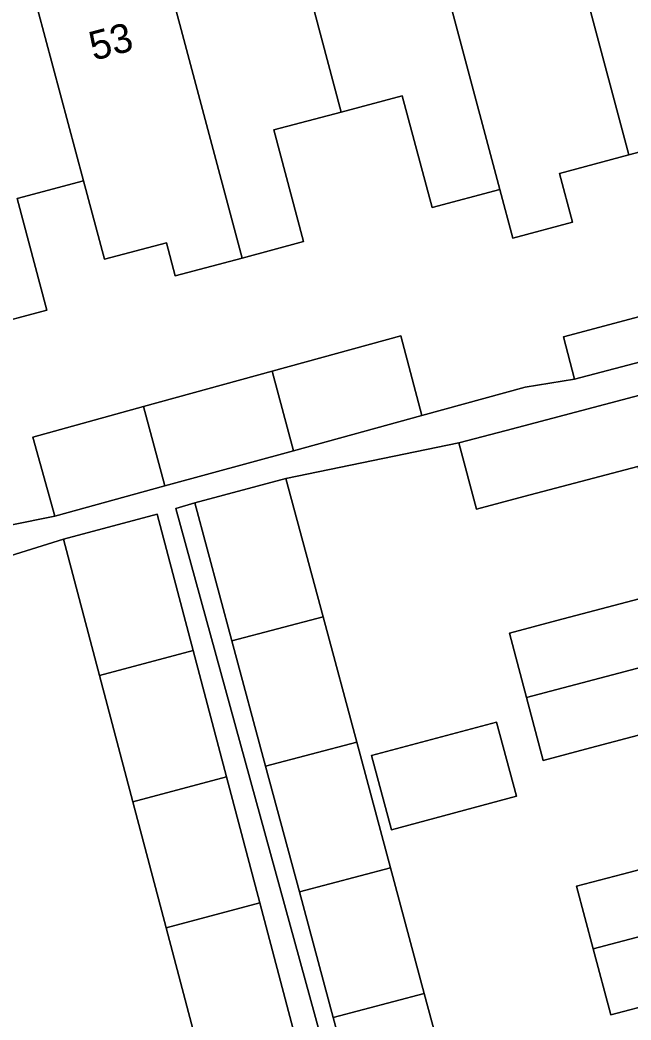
# Model space of a CAD drawing. Extents: x 162542 to 163147, y 380779 to 381521.
# Drawn here: x 162943.37 to 162964.52, y 381061.15 to 381095.77 of the extents above; entities that cross this region are included whole.
import ezdxf

# ---------------------------------------------------------------- set-up
doc = ezdxf.new("R2010")
doc.units = 0
for name, color, linetype in [('IMGEO_Erf', 7, 'Continuous'), ('IMGEO_Pand', 7, 'Continuous'), ('IMGEO_Pand_nummerreeks', 7, 'Continuous'), ('IMGEO_Voetpad_open', 7, 'Continuous')]:
    doc.layers.add(name, color=color, linetype=linetype)

msp = doc.modelspace()

# ---------------------------------------------------------------- linework, layer by layer
at = {"layer": 'IMGEO_Erf'}
for points in [[(162966.533, 381091.654), (162964.441, 381091.096), (162962.04, 381090.455), (162962.49, 381088.768), (162960.429, 381088.219), (162959.979, 381089.905), (162957.634, 381089.28), (162956.604, 381093.145), (162954.49, 381092.581), (162952.16, 381091.96), (162953.19, 381088.095), (162951.058, 381087.526), (162948.745, 381086.909), (162948.439, 381088.057), (162946.293, 381087.485), (162945.569, 381090.202), (162943.27, 381089.589), (162944.3, 381085.724), (162942.136, 381085.147)], [(162943.031, 381078.285), (162944.574, 381078.593), (162943.821, 381081.328), (162947.65, 381082.383), (162952.101, 381083.608), (162956.552, 381084.834), (162957.285, 381082.08), (162960.856, 381083.06), (162962.567, 381083.332), (162962.18, 381084.798), (162965.856, 381085.778)], [(162964.758, 381080.313), (162960.804, 381079.269), (162959.168, 381078.837), (162958.559, 381081.13), (162952.576, 381079.901), (162953.862, 381075.111), (162955.028, 381070.767), (162956.197, 381066.415), (162957.364, 381062.069), (162958.531, 381057.722), (162959.699, 381053.373), (162960.867, 381049.024), (162962.035, 381044.676), (162963.202, 381040.328), (162964.368, 381035.987), (162963.874, 381035.856), (162963.988, 381035.424), (162965.053, 381031.394)], [(162949.589, 381059.97), (162948.434, 381064.339), (162947.28, 381068.705), (162946.126, 381073.072), (162944.876, 381077.8), (162939.108, 381076.001), (162939.716, 381073.724), (162937.801, 381073.209), (162933.966, 381072.177), (162934.559, 381069.971), (162935.129, 381067.853), (162938.991, 381068.892), (162940.87, 381069.398), (162941.471, 381067.148), (162942.049, 381064.981), (162940.178, 381064.477), (162936.303, 381063.434), (162936.892, 381061.244), (162937.479, 381059.064)], [(162967.006, 381071.597), (162963.116, 381070.57), (162961.477, 381070.137), (162960.899, 381072.316), (162960.308, 381074.542), (162961.952, 381074.976), (162965.892, 381076.017)], [(162965.399, 381061.744), (162963.817, 381061.326), (162963.21, 381063.612), (162962.634, 381065.78), (162964.222, 381066.2), (162968.157, 381067.24)]]:
    msp.add_lwpolyline(points, dxfattribs=at)
for points in [[(162954.212, 381061.238), (162953.043, 381065.583), (162951.872, 381069.935), (162950.704, 381074.277), (162949.419, 381079.055), (162948.769, 381078.858), (162959.598, 381039.377), (162960.061, 381039.499), (162958.891, 381043.846), (162957.722, 381048.194), (162956.552, 381052.542), (162955.382, 381056.891)], [(162956.233, 381067.737), (162955.543, 381070.304), (162959.861, 381071.464), (162960.551, 381068.896)]]:
    msp.add_lwpolyline(points, close=True, dxfattribs=at)
at = {"layer": 'IMGEO_Pand'}
for points in [[(162964.441, 381091.096), (162966.533, 381091.654), (162968.842, 381092.269), (162965.956, 381103.091), (162961.56, 381101.919)], [(162964.441, 381091.096), (162961.56, 381101.919), (162957.099, 381100.729), (162959.979, 381089.905), (162960.429, 381088.219), (162962.49, 381088.768), (162962.04, 381090.455)], [(162952.638, 381099.539), (162954.49, 381092.581), (162956.604, 381093.145), (162957.634, 381089.28), (162959.979, 381089.905), (162957.099, 381100.729)], [(162952.638, 381099.539), (162948.177, 381098.349), (162951.058, 381087.526), (162953.19, 381088.095), (162952.16, 381091.96), (162954.49, 381092.581)], [(162948.177, 381098.349), (162943.717, 381097.16), (162945.569, 381090.202), (162946.293, 381087.485), (162948.439, 381088.057), (162948.745, 381086.909), (162951.058, 381087.526)], [(162943.717, 381097.16), (162939.255, 381095.97), (162942.136, 381085.147), (162944.3, 381085.724), (162943.27, 381089.589), (162945.569, 381090.202)], [(162962.18, 381084.798), (162962.567, 381083.332), (162966.249, 381084.305), (162965.856, 381085.778)], [(162952.833, 381080.859), (162957.285, 381082.08), (162956.552, 381084.834), (162952.101, 381083.608)], [(162965.332, 381078.14), (162972.251, 381079.967), (162971.052, 381084.43), (162966.218, 381083.153), (162960.198, 381081.563), (162958.559, 381081.13), (162959.168, 381078.837), (162960.804, 381079.269), (162964.758, 381080.313)], [(162952.833, 381080.859), (162952.101, 381083.608), (162947.65, 381082.383), (162948.381, 381079.637)], [(162948.381, 381079.637), (162947.65, 381082.383), (162943.821, 381081.328), (162944.574, 381078.593)], [(162953.862, 381075.111), (162952.576, 381079.901), (162949.419, 381079.055), (162950.704, 381074.277)], [(162965.332, 381078.14), (162965.892, 381076.017), (162961.952, 381074.976), (162960.308, 381074.542), (162960.899, 381072.316), (162973.42, 381075.619), (162972.251, 381079.967)], [(162949.366, 381073.941), (162948.119, 381078.661), (162944.876, 381077.8), (162946.126, 381073.072)], [(162960.899, 381072.316), (162961.477, 381070.137), (162963.116, 381070.57), (162967.006, 381071.597), (162967.581, 381069.421), (162974.588, 381071.271), (162973.42, 381075.619)], [(162953.862, 381075.111), (162950.704, 381074.277), (162951.872, 381069.935), (162955.028, 381070.767)], [(162950.521, 381069.574), (162949.366, 381073.941), (162946.126, 381073.072), (162947.28, 381068.705)], [(162960.551, 381068.896), (162959.861, 381071.464), (162955.543, 381070.304), (162956.233, 381067.737)], [(162963.21, 381063.612), (162975.757, 381066.923), (162974.588, 381071.271), (162967.581, 381069.421), (162968.157, 381067.24), (162964.222, 381066.2), (162962.634, 381065.78)], [(162955.028, 381070.767), (162951.872, 381069.935), (162953.043, 381065.583), (162956.197, 381066.415)], [(162950.521, 381069.574), (162947.28, 381068.705), (162948.434, 381064.339), (162951.675, 381065.207)], [(162963.21, 381063.612), (162963.817, 381061.326), (162965.399, 381061.744), (162969.326, 381062.781), (162969.872, 381060.714), (162976.925, 381062.575), (162975.757, 381066.923)], [(162957.364, 381062.069), (162956.197, 381066.415), (162953.043, 381065.583), (162954.212, 381061.238)], [(162952.83, 381060.839), (162951.675, 381065.207), (162948.434, 381064.339), (162949.589, 381059.97)], [(162955.382, 381056.891), (162958.531, 381057.722), (162957.364, 381062.069), (162954.212, 381061.238)]]:
    msp.add_lwpolyline(points, close=True, dxfattribs=at)
at = {"layer": 'IMGEO_Voetpad_open'}
for points in [[(162966.249, 381084.305), (162962.567, 381083.332), (162960.856, 381083.06), (162957.285, 381082.08), (162952.833, 381080.859), (162948.381, 381079.637), (162944.574, 381078.593), (162943.031, 381078.285), (162939.577, 381077.373), (162930.599, 381074.852), (162926.293, 381073.693), (162926.089, 381073.641), (162926.384, 381072.578), (162931.213, 381073.877), (162937.189, 381075.485), (162939.108, 381076.001), (162944.876, 381077.8), (162948.119, 381078.661), (162949.366, 381073.941), (162950.521, 381069.574), (162951.675, 381065.207), (162952.83, 381060.839)], [(162959.598, 381039.377), (162948.769, 381078.858), (162949.419, 381079.055), (162952.576, 381079.901), (162958.559, 381081.13), (162960.198, 381081.563), (162966.218, 381083.153)]]:
    msp.add_lwpolyline(points, dxfattribs=at)

# ---------------------------------------------------------------- texts
at = {"layer": 'IMGEO_Pand_nummerreeks'}
msp.add_text('53', height=1, rotation=14.9313, dxfattribs=at).set_placement((162945.922, 381094.352))

doc.saveas('drawing.dxf')
